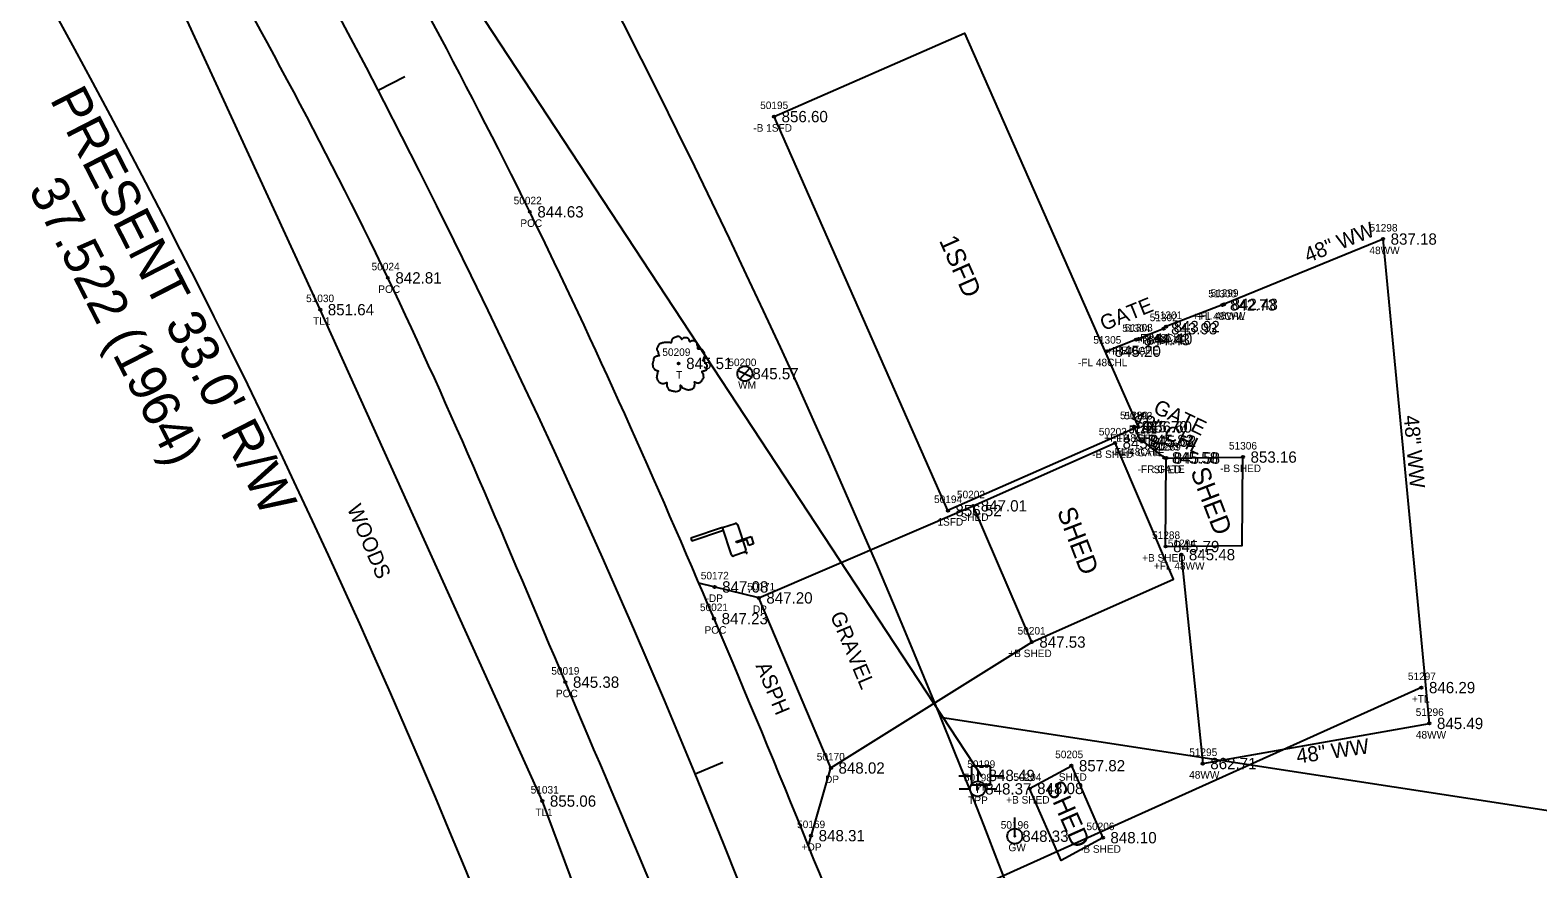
# Model space of a CAD drawing. Extents: x 1378245 to 1381654, y 996521 to 1000567.
# Drawn here: x 1380420.1 to 1380620.1, y 998046 to 998157.3 of the extents above; entities that cross this region are included whole.
import ezdxf

# ---------------------------------------------------------------- set-up
doc = ezdxf.new("R2010")
doc.units = 0
for name, color, linetype in [('RD_EX_Bldg', 7, 'Continuous'), ('RD_EX_Bldg_txCode', 7, 'Continuous'), ('RD_EX_BldgApp', 7, 'Continuous'), ('RD_EX_Driveway', 7, 'Continuous'), ('RD_EX_Driveway_txCode', 7, 'Continuous'), ('RD_EX_DV_Prop', 7, 'Continuous'), ('RD_EX_Fence_Other', 7, 'Continuous'), ('RD_EX_Fence_Other_txCode', 7, 'Continuous'), ('RD_EX_Road', 7, 'Continuous'), ('RD_EX_Road_txCode', 7, 'Continuous'), ('RD_EX_RW', 7, 'Continuous'), ('RD_EX_RW_TX', 7, 'Continuous'), ('RD_EX_SU_Elec', 7, 'Continuous'), ('RD_EX_TX_Bldg_ELEV', 7, 'Continuous'), ('RD_EX_TX_Driveway_ELEV', 7, 'Continuous'), ('RD_EX_TX_Fence_Other_ELEV', 7, 'Continuous'), ('RD_EX_TX_Road_ELEV', 7, 'Continuous'), ('RD_EX_TX_UT_ELEV', 7, 'Continuous'), ('RD_EX_TX_VEG_ELEV', 7, 'Continuous'), ('RD_EX_UT', 7, 'Continuous'), ('RD_EX_UT_txCode', 7, 'Continuous'), ('RD_EX_VEG', 7, 'Continuous'), ('RD_EX_VEG_txCode', 7, 'Continuous'), ('RD_HC_Cl', 7, 'Continuous'), ('RD_HC_Data_Tic', 7, 'Continuous'), ('RD_HC_Survey_ELEV', 7, 'Continuous'), ('RD_SMD_Locator', 7, 'Continuous'), ('RD_TX_Bldg', 7, 'Continuous'), ('RD_TX_Misc2', 7, 'Continuous')]:
    doc.layers.add(name, color=color, linetype=linetype)

msp = doc.modelspace()

# ---------------------------------------------------------------- linework, layer by layer
at = {"layer": 'RD_EX_Bldg'}
for points in [[(1380518.76, 998145.8), (1380544.01, 998156.88), (1380567.08, 998104.61)], [(1380567.08, 998104.61), (1380541.83, 998093.52), (1380518.76, 998145.8)], [(1380552.96, 998076.07), (1380545.19, 998094.15), (1380564, 998102.49)], [(1380552.96, 998076.07), (1380571.77, 998084.41), (1380564, 998102.49)], [(1380570.71, 998088.75), (1380570.8, 998100.48), (1380580.98, 998100.62)], [(1380570.71, 998088.75), (1380580.89, 998088.9), (1380580.98, 998100.62)], [(1380552.67, 998056.64), (1380558.21, 998059.66), (1380562.39, 998050.11)], [(1380562.39, 998050.11), (1380556.85, 998047.09), (1380552.67, 998056.64)]]:
    msp.add_lwpolyline(points, dxfattribs=at)
at = {"layer": 'RD_EX_BldgApp'}
for p, q in [((1380511.92, 998091.26), (1380507.73, 998089.87)), ((1380512.05, 998090.86), (1380507.86, 998089.47)), ((1380511.92, 998091.26), (1380513.58, 998091.81)), ((1380513.11, 998087.66), (1380511.92, 998091.26)), ((1380513.89, 998091.65), (1380515.01, 998088.29)), ((1380507.73, 998089.87), (1380507.86, 998089.47)), ((1380513.73, 998089.41), (1380515.72, 998090.07)), ((1380513.79, 998089.23), (1380513.73, 998089.41)), ((1380515.14, 998089.68), (1380513.79, 998089.23)), ((1380515.4, 998088.88), (1380515.14, 998089.68)), ((1380516.04, 998089.09), (1380515.4, 998088.88)), ((1380515.72, 998090.07), (1380516.04, 998089.09)), ((1380514.85, 998087.98), (1380513.42, 998087.51)), ((1380514.85, 998087.98), (1380515.08, 998088.06)), ((1380515.16, 998087.82), (1380515.04, 998087.78)), ((1380515.08, 998088.06), (1380515.16, 998087.82))]:
    msp.add_line(p, q, dxfattribs=at)
for centre, start, end in [((1380513.66, 998091.57), 18.3234, 108.3234), ((1380514.77, 998088.21), 288.3234, 18.3234), ((1380513.35, 998087.74), 198.3234, 288.3234)]:
    msp.add_arc(centre, 0.25, start, end, dxfattribs=at)
at = {"layer": 'RD_EX_Driveway'}
for p, q in [((1380516.74, 998081.93), (1380545.19, 998094.15)), ((1380526.31, 998059.36), (1380552.96, 998076.07))]:
    msp.add_line(p, q, dxfattribs=at)
msp.add_lwpolyline([(1380523.31, 998049.08), (1380526.31, 998059.36), (1380516.74, 998081.93), (1380508.79, 998083.9)], dxfattribs=at)
at = {"layer": 'RD_EX_DV_Prop'}
msp.add_lwpolyline([(1380346.89, 998389.12), (1380599.47, 998609.82), (1380968.01, 998236), (1380852, 998018.3), (1380541.11, 998066.02)], dxfattribs=at)
at = {"layer": 'RD_EX_Fence_Other'}
for p, q in [((1380578.25, 998120.8), (1380570.77, 998117.94)), ((1380570.44, 998117.65), (1380567.13, 998116.29)), ((1380566.8, 998116.21), (1380562.95, 998114.67)), ((1380566.51, 998104.65), (1380567.35, 998102.82)), ((1380567.63, 998102.72), (1380570.55, 998100.52))]:
    msp.add_line(p, q, dxfattribs=at)
msp.add_lwpolyline([(1380572.8, 998087.67), (1380575.64, 998059.95), (1380605.72, 998065.27), (1380599.57, 998129.55), (1380578.47, 998120.89)], dxfattribs=at)
at = {"layer": 'RD_EX_Road'}
for points in [[(1380571.28, 997900.85), (1380553.84, 997963.23), (1380535.07, 998018.79), (1380510.81, 998079.18), (1380486.36, 998133.16), (1380458.39, 998185.94), (1380428.11, 998238.22), (1380392.69, 998291.14), (1380357.52, 998337.62), (1380319.37, 998385.16), (1380279.26, 998428.68), (1380239.6, 998468.13), (1380183.37, 998518.83)], [(1380551.89, 997897.33), (1380534.24, 997958.2), (1380514.83, 998013.47), (1380491.08, 998070.75), (1380467.52, 998124.4), (1380439.88, 998176.53), (1380409.17, 998228.12), (1380375.89, 998278.45), (1380340.75, 998326.22), (1380303.33, 998371.14), (1380263.98, 998413.97), (1380224.66, 998452.64), (1380168.71, 998504.79)]]:
    msp.add_spline(points, degree=3, dxfattribs=at)
at = {"layer": 'RD_EX_RW'}
for radius in [1193, 1127]:
    msp.add_arc((1379435.86, 997616.44), radius, 14.99564, 47.66422, dxfattribs=at)
at = {"layer": 'RD_EX_SU_Elec'}
msp.add_lwpolyline([(1378514.25, 999944.12), (1378777.7, 999831.22), (1379190.17, 999461.05), (1379403.33, 999174.04), (1379756.94, 998924.25), (1380051.16, 998659.97), (1380327.91, 998390.65), (1380546.23, 998058.37)], dxfattribs=at)
at = {"layer": 'RD_EX_UT'}
for p, q in [((1380514.22, 998110.96), (1380515.55, 998112.41)), ((1380513.98, 998112.11), (1380515.79, 998111.25)), ((1380543.26, 998058.34), (1380544.99, 998058.34)), ((1380547.47, 998059.62), (1380544.97, 998059.62)), ((1380544.97, 998059.62), (1380544.97, 998057.12)), ((1380545.78, 998059.12), (1380545.78, 998057.59)), ((1380547.44, 998058.34), (1380549.26, 998058.34)), ((1380547.47, 998057.12), (1380547.47, 998059.62)), ((1380543.32, 998056.59), (1380544.78, 998056.59)), ((1380544.97, 998057.12), (1380547.47, 998057.12)), ((1380546.78, 998056.59), (1380548.32, 998056.59)), ((1380550.7, 998050.31), (1380550.7, 998052.81))]:
    msp.add_line(p, q, dxfattribs=at)
for centre in [(1380514.89, 998111.69), (1380545.78, 998056.59), (1380550.7, 998050.31)]:
    msp.add_circle(centre, 1, dxfattribs=at)
at = {"layer": 'RD_EX_VEG'}
for points in [[(1380572.26, 997755.47), (1380563.06, 997802.88), (1380548.57, 997859.96), (1380528.6, 997926.15), (1380512.76, 997988.52), (1380488.02, 998054.97), (1380458.55, 998120.18), (1380432.73, 998176.36), (1380395.75, 998235.49), (1380345.67, 998286.69), (1380306.05, 998354.38), (1380256.57, 998407.41), (1380203.97, 998456.66), (1380158.7, 998500.55), (1380112.46, 998542.96), (1380070.42, 998580.38), (1380028.44, 998619.77), (1379982.76, 998660.07), (1379934.04, 998703.39), (1379891.18, 998743.94), (1379841.91, 998788.98), (1379798.41, 998828.62), (1379752.34, 998871.98), (1379716.47, 998899.23)], [(1380604.66, 998070.03), (1380544.29, 998042.85), (1380555.44, 998003.02), (1380568.67, 997935.81)]]:
    msp.add_lwpolyline(points, dxfattribs=at)
for centre, radius in [((1380506.1, 998113.04), 0.125), ((1380506.1, 998113.03), 0.00005)]:
    msp.add_circle(centre, radius, dxfattribs=at)
for points in [[(1380506.17, 998116.62), (1380506.02, 998116.63), (1380505.86, 998116.58), (1380505.73, 998116.53), (1380505.62, 998116.5), (1380505.51, 998116.45), (1380505.36, 998116.36), (1380505.24, 998116.26), (1380505.18, 998116.13), (1380505.16, 998116.02), (1380505.13, 998115.88), (1380505.13, 998115.8), (1380505.07, 998115.78), (1380504.99, 998115.8), (1380504.87, 998115.83), (1380504.74, 998115.83), (1380504.62, 998115.83), (1380504.44, 998115.82), (1380504.27, 998115.82), (1380504.13, 998115.8), (1380503.97, 998115.77), (1380503.78, 998115.71), (1380503.61, 998115.65), (1380503.46, 998115.52), (1380503.33, 998115.28), (1380503.27, 998115.11), (1380503.19, 998114.98), (1380503.27, 998114.76), (1380503.36, 998114.59), (1380503.37, 998114.49), (1380503.41, 998114.27), (1380503.46, 998114.16), (1380503.52, 998114.06), (1380503.48, 998114.05), (1380503.29, 998114.02), (1380503.14, 998113.97), (1380502.93, 998113.86), (1380502.82, 998113.75), (1380502.77, 998113.59), (1380502.76, 998113.41), (1380502.71, 998113.31), (1380502.67, 998113.17), (1380502.66, 998113.14), (1380502.63, 998112.97), (1380502.68, 998112.75), (1380502.69, 998112.57), (1380502.76, 998112.46), (1380502.83, 998112.37), (1380502.92, 998112.25), (1380503.12, 998112.14), (1380503.28, 998112.09), (1380503.38, 998112.07), (1380503.29, 998111.82), (1380503.27, 998111.65), (1380503.21, 998111.45), (1380503.21, 998111.41), (1380503.18, 998111.17), (1380503.26, 998111.01), (1380503.29, 998110.82), (1380503.38, 998110.71), (1380503.52, 998110.56), (1380503.68, 998110.45), (1380503.93, 998110.39), (1380504.13, 998110.4), (1380504.42, 998110.49), (1380504.54, 998110.52), (1380504.53, 998110.44), (1380504.54, 998110.25), (1380504.54, 998110.04), (1380504.62, 998109.87), (1380504.67, 998109.74), (1380504.74, 998109.61), (1380504.91, 998109.5), (1380505.11, 998109.46), (1380505.32, 998109.39), (1380505.54, 998109.35), (1380505.79, 998109.34), (1380506.09, 998109.41), (1380506.23, 998109.47), (1380506.28, 998109.56), (1380506.38, 998109.75), (1380506.36, 998109.86), (1380506.37, 998110.16), (1380506.42, 998110.07), (1380506.51, 998109.9), (1380506.76, 998109.75), (1380506.96, 998109.66), (1380507.19, 998109.59), (1380507.34, 998109.55), (1380507.58, 998109.59), (1380507.77, 998109.62), (1380507.95, 998109.69), (1380508.1, 998109.82), (1380508.19, 998109.96), (1380508.22, 998110.1), (1380508.25, 998110.29), (1380508.28, 998110.37)], [(1380508.28, 998110.37), (1380508.24, 998110.46), (1380508.22, 998110.59), (1380508.25, 998110.57), (1380508.34, 998110.55), (1380508.48, 998110.49), (1380508.59, 998110.45), (1380508.75, 998110.46), (1380508.89, 998110.51), (1380509.12, 998110.65), (1380509.25, 998110.89), (1380509.39, 998111.09), (1380509.43, 998111.25), (1380509.4, 998111.36), (1380509.39, 998111.61), (1380509.29, 998111.74), (1380509.27, 998111.8), (1380509.22, 998112), (1380509.25, 998112.02), (1380509.39, 998112.05), (1380509.58, 998112.11), (1380509.72, 998112.17), (1380509.83, 998112.26), (1380509.87, 998112.37), (1380509.85, 998112.57), (1380509.88, 998112.77), (1380509.84, 998112.85), (1380509.79, 998112.92), (1380509.75, 998113.02), (1380509.68, 998113.1), (1380509.63, 998113.17), (1380509.58, 998113.22), (1380509.52, 998113.3), (1380509.43, 998113.36), (1380509.35, 998113.39), (1380509.33, 998113.46), (1380509.4, 998113.56), (1380509.43, 998113.61), (1380509.44, 998113.72), (1380509.55, 998113.9), (1380509.58, 998114.1), (1380509.55, 998114.31), (1380509.53, 998114.45), (1380509.45, 998114.59), (1380509.35, 998114.71), (1380509.29, 998114.8), (1380509.2, 998114.86), (1380509.04, 998114.92), (1380508.92, 998114.95), (1380508.74, 998114.95), (1380508.64, 998114.97), (1380508.65, 998115), (1380508.65, 998115.07), (1380508.65, 998115.21), (1380508.62, 998115.43), (1380508.54, 998115.68), (1380508.54, 998115.7), (1380508.49, 998115.82), (1380508.38, 998115.92), (1380508.29, 998115.97), (1380508.19, 998116.03), (1380508.07, 998116.05), (1380507.92, 998116.05), (1380507.78, 998116.02), (1380507.68, 998115.97), (1380507.59, 998115.91), (1380507.55, 998115.98), (1380507.5, 998116.13), (1380507.48, 998116.21), (1380507.4, 998116.3), (1380507.29, 998116.4), (1380507.07, 998116.46), (1380506.76, 998116.42), (1380506.61, 998116.32), (1380506.53, 998116.23), (1380506.51, 998116.3), (1380506.41, 998116.4), (1380506.36, 998116.48), (1380506.27, 998116.55), (1380506.19, 998116.6), (1380506.14, 998116.62)]]:
    msp.add_spline(points, degree=3, dxfattribs=at)
at = {"layer": 'RD_HC_Cl'}
msp.add_arc((1379435.86, 997616.44), 1160, 14.99564, 47.66422, dxfattribs=at)
at = {"layer": 'RD_HC_Data_Tic'}
for p, q in [((1380466.22, 998149.3), (1380469.78, 998151.13)), ((1380508.28, 998058.6), (1380511.98, 998060.13))]:
    msp.add_line(p, q, dxfattribs=at)
at = {"layer": 'RD_SMD_Locator'}
for centre, radius in [((1380518.76, 998145.8), 0.15), ((1380486.36, 998133.16), 0.15), ((1380599.57, 998129.55), 0.15), ((1380467.52, 998124.4), 0.15), ((1380458.55, 998120.18), 0.15), ((1380578.25, 998120.8), 0.15), ((1380578.47, 998120.89), 0.15), ((1380566.8, 998116.21), 0.15), ((1380567.13, 998116.29), 0.15), ((1380570.44, 998117.65), 0.15), ((1380570.77, 998117.94), 0.15), ((1380562.95, 998114.67), 0.15), ((1380506.1, 998113.04), 0.075), ((1380514.89, 998111.69), 0.075), ((1380566.51, 998104.65), 0.15), ((1380567.08, 998104.61), 0.15), ((1380564, 998102.49), 0.15), ((1380567.35, 998102.82), 0.15), ((1380567.63, 998102.72), 0.15), ((1380570.55, 998100.52), 0.15), ((1380570.8, 998100.48), 0.15), ((1380580.98, 998100.62), 0.15), ((1380545.19, 998094.15), 0.15), ((1380541.83, 998093.52), 0.15), ((1380570.71, 998088.75), 0.15), ((1380572.8, 998087.67), 0.15), ((1380510.87, 998083.39), 0.15), ((1380516.74, 998081.93), 0.15), ((1380510.81, 998079.18), 0.15), ((1380552.96, 998076.07), 0.15), ((1380491.08, 998070.75), 0.15), ((1380604.66, 998070.03), 0.15), ((1380605.72, 998065.27), 0.15), ((1380526.31, 998059.36), 0.15), ((1380546.23, 998058.37), 0.075), ((1380558.21, 998059.66), 0.15), ((1380575.64, 998059.95), 0.15), ((1380545.78, 998056.59), 0.075), ((1380552.67, 998056.64), 0.15), ((1380488.02, 998054.97), 0.15), ((1380523.68, 998050.38), 0.15), ((1380550.7, 998050.31), 0.075), ((1380562.39, 998050.11), 0.15)]:
    msp.add_circle(centre, radius, dxfattribs=at)

# ---------------------------------------------------------------- texts
at = {"layer": 'RD_EX_Bldg_txCode'}
for s, p in [('50195', (1380516.92, 998146.8)), ('-B 1SFD', (1380516.01, 998143.8)), ('50193', (1380565.24, 998105.61)), ('50203', (1380561.85, 998103.49)), ('+B 1SFD', (1380564.25, 998102.61)), ('51289', (1380569.01, 998101.48)), ('51306', (1380579.12, 998101.62)), ('-B SHED', (1380560.97, 998100.49)), ('SHED', (1380569.12, 998098.48)), ('-B SHED', (1380577.95, 998098.62)), ('50194', (1380539.99, 998094.52)), ('50202', (1380543.03, 998095.15)), ('1SFD', (1380540.44, 998091.52)), ('SHED', (1380543.51, 998092.15)), ('51288', (1380568.92, 998089.75)), ('+B SHED', (1380567.6, 998086.75)), ('50201', (1380551.08, 998077.07)), ('+B SHED', (1380549.84, 998074.07)), ('50205', (1380556.06, 998060.66)), ('50204', (1380550.51, 998057.64)), ('SHED', (1380556.54, 998057.66)), ('+B SHED', (1380549.56, 998054.64)), ('50206', (1380560.21, 998051.11)), ('-B SHED', (1380559.36, 998048.11))]:
    msp.add_text(s, height=1, dxfattribs=at).set_placement(p)
at = {"layer": 'RD_EX_Driveway_txCode'}
for s, p in [('50172', (1380509.04, 998084.39)), ('-DP', (1380509.68, 998081.39)), ('50171', (1380515.19, 998082.93)), ('DP', (1380515.96, 998079.93)), ('50170', (1380524.43, 998060.36)), ('DP', (1380525.53, 998057.36)), ('50169', (1380521.82, 998051.38)), ('+DP', (1380522.42, 998048.38))]:
    msp.add_text(s, height=1, dxfattribs=at).set_placement(p)
at = {"layer": 'RD_EX_Fence_Other_txCode'}
for s, p in [('51298', (1380597.77, 998130.55)), ('48WW', (1380597.76, 998127.55)), ('51300', (1380576.37, 998121.8)), ('51299', (1380576.67, 998121.89)), ('51303', (1380565.29, 998117.29)), ('51302', (1380568.61, 998118.65)), ('51301', (1380569.21, 998118.94)), ('+FL 48CHL', (1380574.31, 998118.8)), ('-FL 48WW', (1380574.91, 998118.89)), ('51305', (1380561.12, 998115.67)), ('51304', (1380564.96, 998117.21)), ('+FR GATE', (1380566.81, 998115.65)), ('-FL 48CHL', (1380566.91, 998115.94)), ('+FL 48CHL', (1380562.86, 998114.21)), ('-FR GATE', (1380563.57, 998114.29)), ('-FL 48CHL', (1380559.09, 998112.67)), ('51290', (1380564.67, 998105.65)), ('51292', (1380565.84, 998103.72)), ('51291', (1380565.84, 998103.82)), ('+FL 48CHL', (1380562.57, 998102.65)), ('51293', (1380568.76, 998101.52)), ('-FL 48CHL', (1380563.5, 998100.82)), ('+FR GATE', (1380564, 998100.72)), ('-FR GATE', (1380567, 998098.52)), ('51294', (1380571.01, 998088.67)), ('+FL 48WW', (1380569.16, 998085.67)), ('51296', (1380603.9, 998066.27)), ('48WW', (1380603.92, 998063.27)), ('51295', (1380573.85, 998060.95)), ('48WW', (1380573.84, 998057.95))]:
    msp.add_text(s, height=1, dxfattribs=at).set_placement(p)
at = {"layer": 'RD_EX_Road_txCode'}
for s, p in [('50022', (1380484.21, 998134.16)), ('POC', (1380485.1, 998131.16)), ('50024', (1380465.36, 998125.4)), ('POC', (1380466.25, 998122.4)), ('50021', (1380508.93, 998080.18)), ('POC', (1380509.54, 998077.18)), ('50019', (1380489.21, 998071.75)), ('POC', (1380489.82, 998068.75))]:
    msp.add_text(s, height=1, dxfattribs=at).set_placement(p)
at = {"layer": 'RD_EX_RW_TX'}
for s, p in [("PRESENT 33.0' R/W", (1380422.6, 998148.11)), ('37.522 (1964)', (1380419.75, 998136.12))]:
    msp.add_text(s, height=5, rotation=297.1291, dxfattribs=at).set_placement(p)
at = {"layer": 'RD_EX_TX_Bldg_ELEV'}
for s, p in [('856.60', (1380519.76, 998145.05)), ('856.60', (1380568.08, 998103.86)), ('845.87', (1380565, 998101.74)), ('845.58', (1380571.8, 998099.73)), ('853.16', (1380581.98, 998099.87)), ('856.52', (1380542.83, 998092.77)), ('847.01', (1380546.19, 998093.4)), ('845.79', (1380571.71, 998088)), ('847.53', (1380553.96, 998075.32)), ('857.82', (1380559.21, 998058.91)), ('848.08', (1380553.67, 998055.89)), ('848.10', (1380563.39, 998049.36))]:
    msp.add_text(s, height=1.5, dxfattribs=at).set_placement(p)
at = {"layer": 'RD_EX_TX_Driveway_ELEV'}
for s, p in [('847.08', (1380511.87, 998082.64)), ('847.20', (1380517.74, 998081.18)), ('848.02', (1380527.31, 998058.61)), ('848.31', (1380524.68, 998049.63))]:
    msp.add_text(s, height=1.5, dxfattribs=at).set_placement(p)
at = {"layer": 'RD_EX_TX_Fence_Other_ELEV'}
for s, p in [('837.18', (1380600.57, 998128.8)), ('842.73', (1380579.25, 998120.05)), ('842.48', (1380579.47, 998120.14)), ('843.93', (1380571.44, 998116.9)), ('843.92', (1380571.77, 998117.19)), ('844.43', (1380567.8, 998115.46)), ('844.40', (1380568.13, 998115.54)), ('845.20', (1380563.95, 998113.92)), ('845.70', (1380567.51, 998103.9)), ('845.83', (1380568.35, 998102.07)), ('845.62', (1380568.63, 998101.97)), ('845.58', (1380571.55, 998099.77)), ('845.48', (1380573.8, 998086.92)), ('845.49', (1380606.72, 998064.52)), ('862.71', (1380576.64, 998059.2))]:
    msp.add_text(s, height=1.5, dxfattribs=at).set_placement(p)
at = {"layer": 'RD_EX_TX_Road_ELEV'}
for s, p in [('844.63', (1380487.36, 998132.41)), ('842.81', (1380468.52, 998123.65)), ('847.23', (1380511.81, 998078.43)), ('845.38', (1380492.08, 998070))]:
    msp.add_text(s, height=1.5, dxfattribs=at).set_placement(p)
at = {"layer": 'RD_EX_TX_UT_ELEV'}
for s, p in [('845.57', (1380515.89, 998110.94)), ('848.37', (1380546.78, 998055.84)), ('848.33', (1380551.7, 998049.56))]:
    msp.add_text(s, height=1.5, dxfattribs=at).set_placement(p)
at = {"layer": 'RD_EX_TX_VEG_ELEV'}
for s, p in [('851.64', (1380459.55, 998119.43)), ('845.51', (1380507.1, 998112.29)), ('846.29', (1380605.66, 998069.28)), ('855.06', (1380489.02, 998054.22))]:
    msp.add_text(s, height=1.5, dxfattribs=at).set_placement(p)
at = {"layer": 'RD_EX_UT'}
msp.add_text('T', height=1, dxfattribs=at).set_placement((1380545.36, 998056.06))
at = {"layer": 'RD_EX_UT_txCode'}
for s, p in [('50200', (1380512.7, 998112.69)), ('WM', (1380513.99, 998109.69)), ('50199', (1380544.39, 998059.37)), ('50198', (1380543.95, 998057.59)), ('PP', (1380545.45, 998056.37)), ('TPP', (1380544.52, 998054.59)), ('50196', (1380548.84, 998051.31)), ('GW', (1380549.86, 998048.31))]:
    msp.add_text(s, height=1, dxfattribs=at).set_placement(p)
at = {"layer": 'RD_EX_VEG_txCode'}
for s, p in [('51030', (1380456.67, 998121.18)), ('TL1', (1380457.61, 998118.18)), ('50209', (1380503.94, 998114.04)), ('T', (1380505.78, 998111.04)), ('51297', (1380602.86, 998071.03)), ('+TL', (1380603.4, 998068.03)), ('51031', (1380486.47, 998055.97)), ('TL1', (1380487.08, 998052.97))]:
    msp.add_text(s, height=1, dxfattribs=at).set_placement(p)
at = {"layer": 'RD_HC_Survey_ELEV'}
msp.add_text('848.49', height=1.5, dxfattribs=at).set_placement((1380547.23, 998057.62))
at = {"layer": 'RD_TX_Bldg'}
for s, rotation, p in [('1SFD', 293.8521, (1380540.62, 998129.36)), ('SHED', 290.9988, (1380573.97, 998098.71)), ('SHED', 290.9988, (1380556.27, 998093.43)), ('SHED', 293.8629, (1380554.76, 998057))]:
    msp.add_text(s, height=2.5, rotation=rotation, dxfattribs=at).set_placement(p)
at = {"layer": 'RD_TX_Misc2'}
for s, rotation, p in [('48" WW', 22.0203, (1380589.61, 998126.38)), ('GATE', 22.0203, (1380562.51, 998117.32)), ('48" CHL', 334.2275, (1380566.07, 998105.21)), ('GATE', 334.2275, (1380568.93, 998106.57)), ('48" WW', 274.9578, (1380602.31, 998106.1)), ('WOODS', 293.0879, (1380462.07, 998093.83)), ('GRAVEL', 292.8744, (1380526.16, 998079.63)), ('ASPH', 292.6194, (1380516.28, 998072.93)), ('48" WW', 8.1865, (1380588.2, 998059.94))]:
    msp.add_text(s, height=2, rotation=rotation, dxfattribs=at).set_placement(p)

doc.saveas('drawing.dxf')
